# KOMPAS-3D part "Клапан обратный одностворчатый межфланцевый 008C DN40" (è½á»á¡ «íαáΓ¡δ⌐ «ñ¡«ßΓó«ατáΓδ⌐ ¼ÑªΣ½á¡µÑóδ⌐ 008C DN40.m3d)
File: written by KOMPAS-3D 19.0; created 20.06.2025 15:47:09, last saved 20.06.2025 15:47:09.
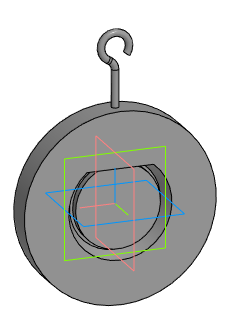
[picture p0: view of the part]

Document properties: Полное имя файла: E:\Dendor Работа Сачек\3D для проектировщиков\5.1 Тип 008C. Клапан обратный одностворчатый межфланцевый\stp_Клапан обратный одностворчатый межфланцевый 008C\Клапан обратный одностворчатый межфланцевый 008C DN40.m3d

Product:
- Part/product: Клапан обратный одностворчатый межфланцевый 008C DN40

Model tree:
1. Операция без истории:1  (labels: Клапан обратный одностворчатый межфланцевый 008C DN40)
